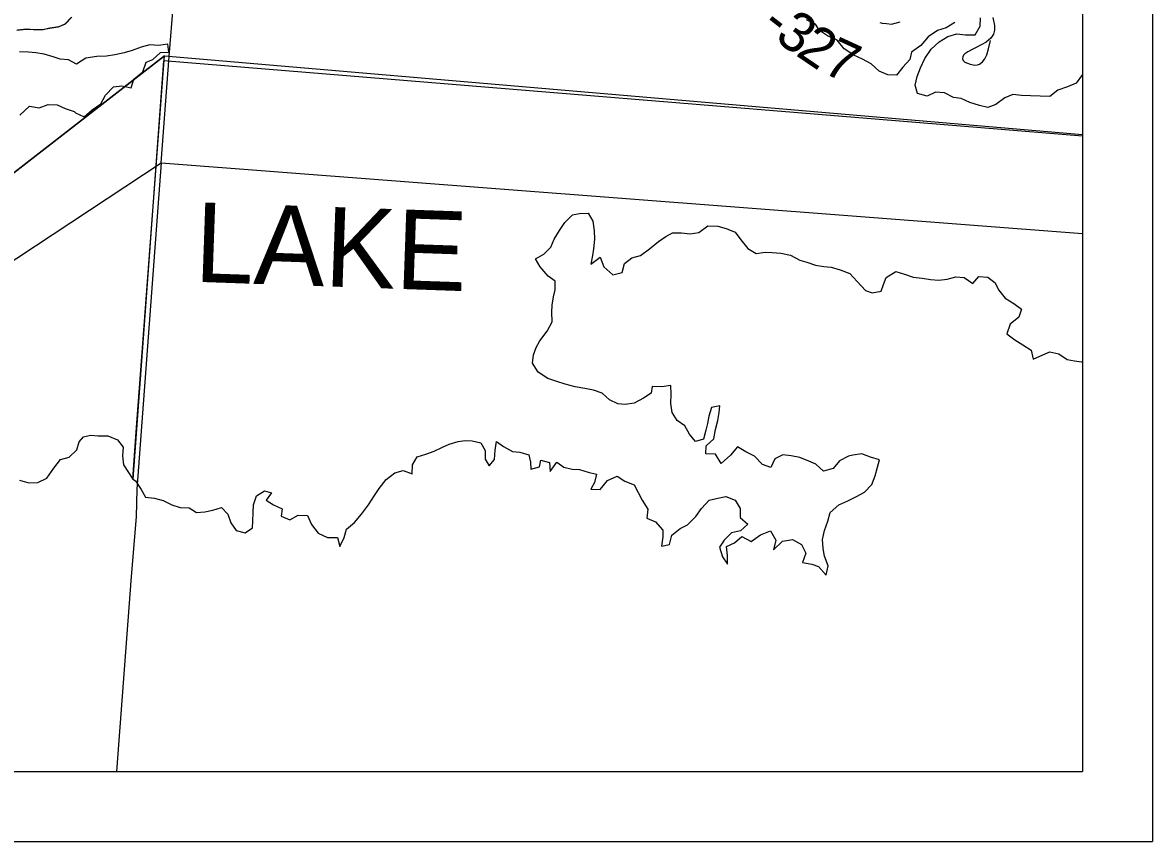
# Model space of a CAD drawing. Extents: x 0 to 40.4, y 0 to 22.
# Drawn here: x 7.886 to 9.5, y 14 to 15.17 of the extents above; entities that cross this region are included whole.
import ezdxf

# ---------------------------------------------------------------- set-up
doc = ezdxf.new("R2010")
doc.units = 0
for name, color, linetype in [('GM_X_Adjacent_County', 7, 'Continuous'), ('GM_X_Corporation', 7, 'Continuous'), ('GM_X_County', 7, 'Continuous'), ('GM_X_County_Road', 7, 'Continuous'), ('GM_X_County_Road_Text', 7, 'Continuous'), ('GM_X_Major_Lake', 7, 'Continuous'), ('GM_X_Major_Lake_Text', 7, 'Continuous'), ('GM_X_Township', 7, 'Continuous'), ('SH_Data', 7, 'Continuous')]:
    doc.layers.add(name, color=color, linetype=linetype)

msp = doc.modelspace()

# ---------------------------------------------------------------- linework, layer by layer
at = {"layer": 'GM_X_Adjacent_County'}
for points in [[(8.0846, 14.9692), (8.0498, 14.5033), (8.0488, 14.4634), (8.0414, 14.3782), (8.0206, 14.1)], [(8.0206, 14.1), (8.0206, 14.1)]]:
    msp.add_lwpolyline(points, dxfattribs=at)
at = {"layer": 'GM_X_Corporation'}
msp.add_lwpolyline([(7.9558, 15.177), (7.9467, 15.1672), (7.9373, 15.1631), (7.9248, 15.1612), (7.9149, 15.159), (7.9021, 15.159), (7.8915, 15.1598), (7.8782, 15.1584)], dxfattribs=at)
at = {"layer": 'GM_X_County'}
for points in [[(2.6, 14.9098), (3.7816, 14.849), (3.7947, 14.8444), (4.3781, 14.8049), (4.5187, 14.7962), (4.7718, 14.7855), (4.9113, 14.7777), (5.1259, 14.7632), (5.4221, 14.7453), (5.6303, 14.7317), (5.757, 14.7237), (5.765, 14.7235), (5.7951, 14.7228), (5.8513, 14.7168), (5.9456, 14.7103), (6.2034, 14.693), (6.2494, 14.69), (6.369, 14.682), (6.4224, 14.6785), (7.5441, 14.6124), (8.0846, 14.9692), (9.4, 14.8681)], [(9.4, 14.8681), (9.4, 14.8681)]]:
    msp.add_lwpolyline(points, dxfattribs=at)
at = {"layer": 'GM_X_County_Road'}
for points in [[(9.1106, 15.1698), (9.1141, 15.1689), (9.1202, 15.168), (9.1276, 15.1673), (9.1399, 15.1707)], [(9.2719, 15.177), (9.2746, 15.1654), (9.2744, 15.1589), (9.2732, 15.1528), (9.2692, 15.1474), (9.2628, 15.1415), (9.2483, 15.134), (9.2446, 15.132), (9.2363, 15.1279), (9.2321, 15.1248), (9.2304, 15.123), (9.2292, 15.1207), (9.2289, 15.1178), (9.2299, 15.1155), (9.2322, 15.113), (9.2398, 15.1103), (9.2464, 15.1088), (9.2501, 15.1093), (9.2529, 15.1103), (9.2574, 15.1137), (9.2605, 15.1178), (9.2634, 15.1237), (9.2659, 15.1321), (9.2688, 15.1437)]]:
    msp.add_lwpolyline(points, dxfattribs=at)
at = {"layer": 'GM_X_Major_Lake'}
for p, q in [((7.4365, 14.6157), (8.0892, 15.1222)), ((8.0892, 15.1222), (9.4, 15.0099)), ((8.0877, 15.1149), (8.0438, 14.5173)), ((9.4, 15.0074), (8.0877, 15.1149)), ((8.0438, 14.5173), (8.0483, 14.5781))]:
    msp.add_line(p, q, dxfattribs=at)
for points in [[(7.9566, 15.1773), (7.9475, 15.1675), (7.938, 15.1633), (7.9255, 15.1615), (7.9157, 15.1592), (7.9028, 15.1593), (7.8922, 15.1601), (7.879, 15.1586)], [(9.2177, 15.1698), (9.2055, 15.1622), (9.1931, 15.1581), (9.1798, 15.1491), (9.1691, 15.137), (9.1559, 15.1271), (9.1536, 15.1169), (9.1437, 15.106), (9.1346, 15.0946), (9.1221, 15.095), (9.11, 15.1), (9.0983, 15.1107), (9.0862, 15.1172), (9.0738, 15.1229), (9.0598, 15.1321), (9.0497, 15.1446), (9.0361, 15.1507), (9.0248, 15.158), (9.0188, 15.1675), (9.0059, 15.1736)], [(9.4, 15.0955), (9.3909, 15.083), (9.3788, 15.0777), (9.3648, 15.0732), (9.3534, 15.0638), (9.3398, 15.0642), (9.3258, 15.0651), (9.3129, 15.0655), (9.3005, 15.0667), (9.2891, 15.0622), (9.2766, 15.0527), (9.2648, 15.0482), (9.2531, 15.0513), (9.2395, 15.0555), (9.2267, 15.0609), (9.2161, 15.0624), (9.2029, 15.0693), (9.19, 15.0701), (9.1783, 15.0645), (9.1647, 15.0683), (9.1613, 15.0801), (9.164, 15.0926), (9.1686, 15.1051), (9.1751, 15.1184), (9.1839, 15.1316), (9.1953, 15.1422), (9.2078, 15.1497), (9.2206, 15.1534), (9.2331, 15.1519), (9.2467, 15.1518), (9.254, 15.1643), (9.2544, 15.1764)], [(7.9621, 15.0404), (7.9745, 15.035), (7.9859, 15.0448), (7.9981, 15.0535), (8.0049, 15.066), (8.0163, 15.0777), (8.028, 15.0792), (8.0413, 15.0761), (8.0455, 15.0886), (8.058, 15.0992), (8.063, 15.1128), (8.0724, 15.1169), (8.0834, 15.1267), (8.0955, 15.1275), (8.0937, 15.1388), (8.0808, 15.137), (8.068, 15.1378), (8.0559, 15.1344), (8.043, 15.1296), (8.0313, 15.1262), (8.018, 15.1236), (8.0063, 15.1214), (7.9927, 15.121), (7.9768, 15.1188), (7.9635, 15.1101), (7.9518, 15.1163), (7.9401, 15.1174), (7.9303, 15.1205), (7.9174, 15.1244), (7.9053, 15.1263), (7.8947, 15.1275), (7.8819, 15.1279)], [(8.0483, 14.5781), (8.0892, 15.1222), (7.4365, 14.6157), (6.4626, 14.6755)], [(7.8823, 15.0373), (7.8963, 15.0501), (7.9103, 15.0478), (7.9228, 15.0527), (7.9357, 15.0522), (7.9474, 15.0469), (7.9602, 15.0427), (7.9621, 15.0404)], [(9.072, 14.5519), (9.0659, 14.55), (9.0531, 14.5438), (9.0441, 14.5327), (9.0305, 14.5289), (9.0191, 14.5386), (9.0093, 14.5431), (8.9964, 14.5483), (8.9839, 14.5505), (8.9722, 14.5523), (8.9609, 14.5462), (8.9553, 14.534), (8.9432, 14.5381), (8.9317, 14.5502), (8.9192, 14.5565), (8.9075, 14.5637), (8.8973, 14.5515), (8.8842, 14.54), (8.8762, 14.5532), (8.8622, 14.5535), (8.8625, 14.5649), (8.8738, 14.5748), (8.8759, 14.5885), (8.8793, 14.6014), (8.8811, 14.6124), (8.8821, 14.6219), (8.8701, 14.6199), (8.8667, 14.6074), (8.8645, 14.5967), (8.862, 14.5872), (8.859, 14.5747), (8.8477, 14.5712), (8.8389, 14.5818), (8.8324, 14.5935), (8.8211, 14.601), (8.8142, 14.6127), (8.8122, 14.6256), (8.8125, 14.6388), (8.8124, 14.6513), (8.7992, 14.6493), (8.7856, 14.6496), (8.7841, 14.6401), (8.7732, 14.6329), (8.7597, 14.626), (8.7468, 14.624), (8.7366, 14.625), (8.7245, 14.6306), (8.7142, 14.64), (8.7017, 14.6445), (8.6892, 14.6467), (8.6756, 14.6493), (8.6612, 14.6529), (8.6495, 14.6567), (8.6366, 14.6611), (8.6229, 14.6701), (8.6145, 14.683), (8.6163, 14.6951), (8.6201, 14.7054), (8.6253, 14.7149), (8.6354, 14.7286), (8.6429, 14.7423), (8.6424, 14.7559), (8.6427, 14.7658), (8.6449, 14.778), (8.6471, 14.7878), (8.647, 14.8), (8.6372, 14.8075), (8.6257, 14.8207), (8.6189, 14.832), (8.6309, 14.8389), (8.641, 14.8488), (8.6455, 14.8602), (8.6534, 14.8724), (8.6608, 14.8838), (8.6717, 14.8949), (8.6819, 14.8969), (8.694, 14.8973), (8.7009, 14.886), (8.7029, 14.872), (8.7033, 14.8602), (8.7019, 14.8466), (8.7005, 14.8367), (8.6979, 14.8246), (8.7114, 14.8345), (8.7168, 14.8205), (8.7294, 14.8092), (8.7426, 14.8127), (8.7459, 14.8253), (8.7564, 14.8337), (8.7689, 14.8368), (8.7817, 14.8464), (8.7948, 14.8567), (8.805, 14.864), (8.8148, 14.8694), (8.8276, 14.8694), (8.8397, 14.8676), (8.8522, 14.8696), (8.8653, 14.8792), (8.8793, 14.8789), (8.8911, 14.8756), (8.9043, 14.87)], [(8.9043, 14.87), (8.9123, 14.8594), (8.9222, 14.847), (8.934, 14.8398), (8.9472, 14.8414), (8.9571, 14.8411), (8.9695, 14.8401), (8.9832, 14.8371), (8.9964, 14.83), (9.0063, 14.8271), (9.0188, 14.823), (9.0309, 14.8212), (9.0411, 14.8201), (9.0543, 14.8164), (9.068, 14.8112), (9.0783, 14.7995), (9.0901, 14.7867), (9.0999, 14.7833), (9.1124, 14.7857), (9.1161, 14.7956), (9.1198, 14.8055), (9.1334, 14.8139), (9.1459, 14.8102), (9.1584, 14.8057), (9.1712, 14.8043), (9.1829, 14.8025), (9.195, 14.8014), (9.2068, 14.803), (9.2192, 14.8065), (9.2313, 14.8055), (9.2435, 14.7968), (9.2521, 14.8068), (9.2649, 14.8057), (9.2756, 14.7978), (9.2802, 14.788), (9.2897, 14.7759), (9.3022, 14.7681), (9.3129, 14.7602), (9.3092, 14.7488), (9.2971, 14.7388), (9.2923, 14.7248), (9.3033, 14.7165), (9.3151, 14.7094), (9.3268, 14.7015), (9.3296, 14.689), (9.3394, 14.6929), (9.3533, 14.6994), (9.3666, 14.6965), (9.3783, 14.6882), (9.3886, 14.6864), (9.3988, 14.6849), (9.4, 14.6844)], [(7.8821, 14.516), (7.8954, 14.5122), (7.9082, 14.5126), (7.9211, 14.5187), (7.9309, 14.5331), (7.9407, 14.5456), (7.9528, 14.549), (7.9641, 14.5593), (7.9675, 14.5707), (7.9736, 14.578), (7.9834, 14.5803), (7.9942, 14.5795), (8.0084, 14.5791), (8.022, 14.5738), (8.0303, 14.5632), (8.0292, 14.5507), (8.0307, 14.5378), (8.0438, 14.5173)], [(8.0438, 14.5173), (8.0476, 14.5149), (8.0556, 14.5024), (8.0621, 14.4915), (8.075, 14.4901), (8.0874, 14.4871), (8.0996, 14.4808), (8.1117, 14.477), (8.1242, 14.4764), (8.1348, 14.47), (8.1469, 14.4708), (8.1582, 14.4732), (8.1707, 14.4771), (8.1798, 14.4673), (8.1837, 14.4548), (8.1917, 14.4439), (8.2045, 14.4405), (8.2147, 14.4478), (8.2154, 14.4573), (8.2157, 14.4698), (8.2164, 14.4808), (8.2204, 14.4937), (8.2321, 14.5006), (8.242, 14.498), (8.2345, 14.4874), (8.2447, 14.4806), (8.2572, 14.475), (8.2558, 14.4644), (8.2683, 14.4592), (8.28, 14.4661), (8.2932, 14.4654), (8.2993, 14.4526), (8.3088, 14.4401), (8.3221, 14.4341), (8.3361, 14.4342), (8.3396, 14.4214), (8.3455, 14.4339), (8.3489, 14.4461), (8.3605, 14.4556), (8.3707, 14.4675), (8.3804, 14.4808), (8.389, 14.4941), (8.3957, 14.504), (8.4055, 14.517), (8.4179, 14.5262), (8.43, 14.53), (8.4428, 14.5248), (8.4435, 14.5377), (8.4499, 14.5491), (8.4623, 14.553), (8.4744, 14.5576), (8.4861, 14.563), (8.4959, 14.5676), (8.5083, 14.5711), (8.5185, 14.5727), (8.5283, 14.572), (8.5408, 14.5695), (8.5469, 14.5581), (8.547, 14.546), (8.5528, 14.5362), (8.5602, 14.5457), (8.5613, 14.559), (8.5631, 14.5711), (8.5734, 14.564), (8.5859, 14.5569), (8.5965, 14.5558), (8.6093, 14.5521), (8.6117, 14.5415), (8.6125, 14.5317), (8.6246, 14.5348), (8.6268, 14.5443), (8.6389, 14.5413), (8.6401, 14.5285), (8.6495, 14.5418), (8.6593, 14.5343), (8.6715, 14.5317), (8.6817, 14.5314), (8.6942, 14.5273), (8.7063, 14.5247), (8.7033, 14.5126), (8.6981, 14.5031), (8.7113, 14.5028), (8.7218, 14.5157), (8.7354, 14.5215), (8.7464, 14.5144), (8.76, 14.5092), (8.7711, 14.4873), (8.7792, 14.4744), (8.7781, 14.4615), (8.7902, 14.4563), (8.8009, 14.4446), (8.801, 14.4348), (8.7988, 14.4219), (8.8105, 14.4242), (8.8138, 14.4375), (8.8258, 14.4467), (8.836, 14.4521), (8.848, 14.4643), (8.8559, 14.4757), (8.8671, 14.4872), (8.8796, 14.4903)], [(8.8796, 14.4903), (8.8909, 14.4926), (8.9042, 14.4874), (8.9111, 14.4753), (8.9115, 14.4628), (8.9222, 14.4531), (8.9117, 14.4435), (8.8988, 14.4408), (8.8883, 14.4304), (8.8816, 14.4202), (8.8862, 14.4066), (8.8934, 14.396), (8.8934, 14.4085), (8.8918, 14.421), (8.9031, 14.4264), (8.9136, 14.4356), (8.9272, 14.4284), (8.9404, 14.438), (8.9544, 14.4434), (8.9624, 14.4302), (8.9591, 14.4165), (8.9718, 14.4287), (8.9858, 14.4311), (8.9987, 14.424), (9.0052, 14.4119), (9.0004, 14.3986), (9.0136, 14.3961), (9.0231, 14.3927), (9.0341, 14.3803), (9.0371, 14.3936), (9.0317, 14.4076), (9.0297, 14.4182), (9.0289, 14.431), (9.0315, 14.4443), (9.0363, 14.4572), (9.04, 14.4698), (9.0524, 14.4805), (9.0652, 14.4866), (9.0773, 14.4924), (9.0889, 14.4986), (9.0994, 14.51), (9.1039, 14.5222), (9.1072, 14.5343), (9.1102, 14.5449), (9.0973, 14.549), (9.0848, 14.5535), (9.072, 14.5519)]]:
    msp.add_lwpolyline(points, dxfattribs=at)
at = {"layer": 'GM_X_Township'}
msp.add_lwpolyline([(8.0846, 14.9692), (8.096, 15.1213), (8.108, 15.2741), (8.1112, 15.3285), (8.1141, 15.384), (8.1155, 15.405), (8.1199, 15.4715), (8.1241, 15.5213), (8.1269, 15.5514), (8.127, 15.57), (8.1633, 16.0818), (8.1652, 16.1082), (8.2004, 16.6154), (8.2342, 17.0906), (8.241, 17.1909), (8.1794, 17.1936), (7.7202, 17.2134)], dxfattribs=at)
at = {"layer": 'SH_Data'}
for p, q in [((9.5, 21), (9.5, 14)), ((9.4, 20.9), (9.4, 14.1)), ((2.6, 14.1), (9.4, 14.1)), ((2.5, 14), (9.5, 14))]:
    msp.add_line(p, q, dxfattribs=at)

# ---------------------------------------------------------------- texts
at = {"layer": 'GM_X_County_Road_Text'}
for s, rotation, p in [('3', 323.9091, (8.959, 15.1455)), ('-', 322.1082, (8.939, 15.161)), ('2', 325.9325, (8.9891, 15.1236)), ('7', 335.3397, (9.0269, 15.099))]:
    msp.add_text(s, height=0.0568, rotation=rotation, dxfattribs=at).set_placement(p)
at = {"layer": 'GM_X_Major_Lake_Text'}
msp.add_text('LAKE', height=0.11363, rotation=358.0002, dxfattribs=at).set_placement((8.131, 14.7994))

doc.saveas('drawing.dxf')
